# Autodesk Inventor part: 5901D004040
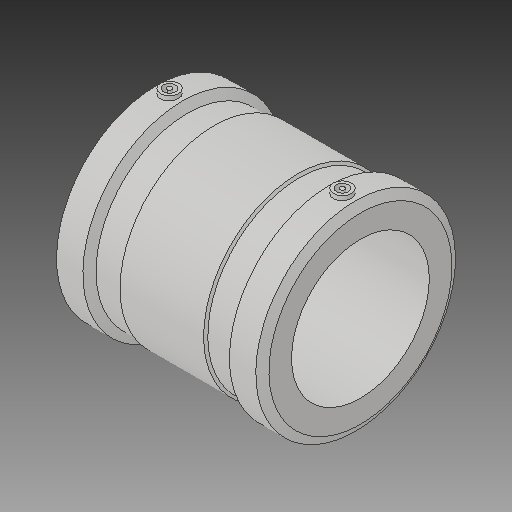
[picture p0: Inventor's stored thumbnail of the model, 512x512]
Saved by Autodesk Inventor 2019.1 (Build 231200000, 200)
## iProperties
Created: 2017-06
Part Number: 5901D004040
Material: Generic
Description: PLASSON COUPLER 4''DIPS
Document SubType Name: Modeling
Designer: KIM
Mass: 96874 g
Surface Area: 34549.7 cm^2
Volume: 96874 cm^3
Density: 1 g/cm^3
Appearance: Default
Author: KIM
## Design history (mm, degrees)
derived "5901D.ipt"
feature "Solid1::5901D.ipt"
tag "TaggingFeature1"
body "Solid1"
other parameters: "d13" = 172.974, "d15" = 85.09, "d16" = 85.09, "d17" = 114.1, "d22" = 172.212, "d23" = 155.956, "d24" = 151.54656, "d25" = 150 deg, "d26" = 69.1896, "d27" = 120 deg, "d29" = 86.106, "d35" = 15, "d39" = 0, "d40" = 4, "d41" = 14, "d42" = 0, "d44" = 29.7815, "d45" = 114.1, "d47" = 0, "d48" = 82.66176, "d49" = 29.7815, "d50" = 60 deg, "d57" = 65.786, "d58" = 29.7815, "d62" = 114.1, "d65" = 282.448, "d67" = 5.27613, "d68" = 21.15863, "d69" = 21.80789, "d70" = 21.71015, "d71" = 20.5722, "d72" = 20.71531, "d73" = 561.2638, "d76" = 69.1896, "d77" = 151.54656, "d_" = 114.1, "L_" = 172.974, "L_1" = 85.09, "D_" = 155.956, "A_" = 86.106, "A_1" = 25.4, "d60" = 187.96
